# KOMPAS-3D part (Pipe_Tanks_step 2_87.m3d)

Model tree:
1. X Axis
2. Y Axis
3. Z Axis  (labels: Valve Dy 50; Pipe Dn 50)
     Òîëùèíà ñòåíêè 1 = 1

Referenced files in C:\Documents and Settings\kashirsky\Мои документы\Camtasia Studio\Pipelines3D\Tanks\: Tanks_step 4.a3d
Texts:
  Pipe Dn 50
  Steel ASTM A295
  Three Point Plane
  Plane at Angle
  Line and Point Plane
  Axis through Two Vertices
  Axis of Feature
  Axis of Conical Surface
  Axis through Edge
  Trim by Surface
  Trim by Sketch
  Feature with No History
  Intersection Axis of Two Planes
  Two Line Plane
  Line and Face Plane
  Bend by line
  Hole in sheet body
  Cut in sheet body
  Point in CM
  Linear Dimension from Line to Point
  Surface Finish Symbol
  Geometric Tolerance Symbol
  Leader #1
  Leader #2
  Leader #3
  Shape Deviations and Datum
  Node point number
  Mark of coordination axis
  Node point designation
  Mark/Reference designation with leader
  Mark/reference designation on line
  Mark/Reference designation without leader
  Valve Dy 50
  Plane of section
